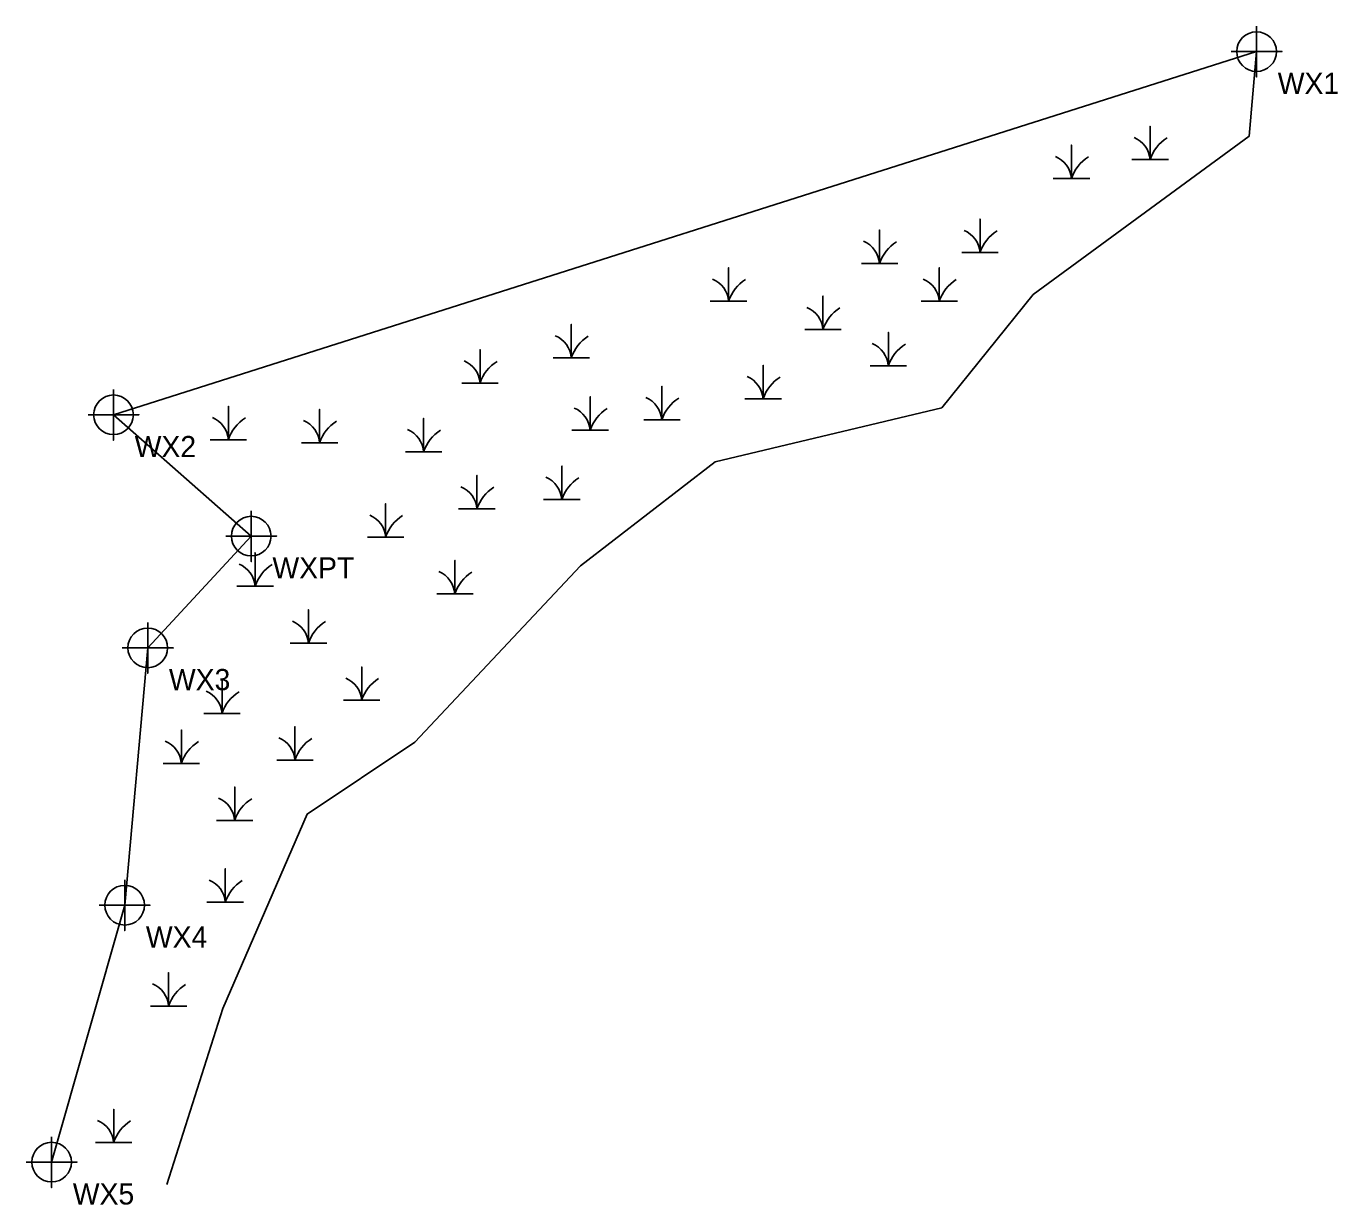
# Model space of a CAD drawing. Extents: x 2171061 to 2188174, y 801741 to 821647.
# Drawn here: x 2178080.8 to 2178235.5, y 808000.7 to 808139.8 of the extents above; entities that cross this region are included whole.
import ezdxf

# ---------------------------------------------------------------- set-up
doc = ezdxf.new("R2010")
doc.units = 0
for name, color, linetype in [('Exist Environmental Wetland Boundary', 7, 'Continuous'), ('Exist Environmental Wetland Boundary Cogo Comment', 7, 'Continuous'), ('Exist Environmental Wetland Boundary Cogo Point CELL', 7, 'Continuous'), ('Exist Hydro Swamp or Marsh', 7, 'Continuous')]:
    doc.layers.add(name, color=color, linetype=linetype)

msp = doc.modelspace()

# ---------------------------------------------------------------- linework, layer by layer
at = {"layer": 'Exist Environmental Wetland Boundary'}
for points in [[(2178225.95, 808136.81), (2178091.09, 808093.95), (2178107.34, 808079.63), (2178095.13, 808066.44), (2178092.41, 808036.07), (2178083.79, 808005.75)], [(2178225.95, 808136.81), (2178225.06, 808126.82), (2178199.61, 808108.15), (2178188.8, 808094.78), (2178162.08, 808088.41), (2178146.17, 808076.11), (2178126.66, 808055.31), (2178113.94, 808046.82), (2178103.97, 808023.9), (2178097.4, 808003.11)]]:
    msp.add_lwpolyline(points, dxfattribs=at)
at = {"layer": 'Exist Environmental Wetland Boundary Cogo Point CELL'}
for points in [[(2178225.95, 808139.81), (2178225.95, 808133.81), (2178225.95, 808136.81), (2178228.95, 808136.81), (2178222.95, 808136.81)], [(2178091.09, 808096.95), (2178091.09, 808090.95), (2178091.09, 808093.95), (2178094.09, 808093.95), (2178088.09, 808093.95)], [(2178107.34, 808082.63), (2178107.34, 808076.63), (2178107.34, 808079.63), (2178110.34, 808079.63), (2178104.34, 808079.63)], [(2178095.13, 808069.44), (2178095.13, 808063.44), (2178095.13, 808066.44), (2178098.13, 808066.44), (2178092.13, 808066.44)], [(2178092.41, 808039.07), (2178092.41, 808033.07), (2178092.41, 808036.07), (2178095.41, 808036.07), (2178089.41, 808036.07)], [(2178083.79, 808008.75), (2178083.79, 808002.75), (2178083.79, 808005.75), (2178086.79, 808005.75), (2178080.79, 808005.75)]]:
    msp.add_lwpolyline(points, dxfattribs=at)
for centre in [(2178225.95, 808136.81), (2178091.09, 808093.95), (2178107.34, 808079.63), (2178095.13, 808066.44), (2178092.41, 808036.07), (2178083.79, 808005.75)]:
    msp.add_circle(centre, 2.34, dxfattribs=at)
at = {"layer": 'Exist Hydro Swamp or Marsh'}
for p, q in [((2178213.38, 808125.85), (2178213.38, 808125.85)), ((2178204.11, 808123.62), (2178204.11, 808123.62)), ((2178193.33, 808114.88), (2178193.33, 808114.88)), ((2178181.47, 808113.59), (2178181.47, 808113.59)), ((2178163.65, 808109.14), (2178163.65, 808109.14)), ((2178188.52, 808109.14), (2178188.52, 808109.14)), ((2178174.79, 808105.79), (2178174.79, 808105.79)), ((2178145.1, 808102.45), (2178145.1, 808102.45)), ((2178182.51, 808101.51), (2178182.51, 808101.51)), ((2178134.34, 808099.48), (2178134.34, 808099.48)), ((2178167.74, 808097.63), (2178167.74, 808097.63)), ((2178147.32, 808093.91), (2178147.32, 808093.91)), ((2178155.79, 808095.15), (2178155.79, 808095.15)), ((2178104.65, 808092.8), (2178104.65, 808092.8)), ((2178115.41, 808092.43), (2178115.41, 808092.43)), ((2178127.68, 808091.36), (2178127.68, 808091.36)), ((2178133.96, 808084.63), (2178133.96, 808084.63)), ((2178143.98, 808085.74), (2178143.98, 808085.74)), ((2178123.2, 808081.29), (2178123.2, 808081.29)), ((2178107.8, 808075.51), (2178107.8, 808075.51)), ((2178131.37, 808074.6), (2178131.37, 808074.6)), ((2178114.09, 808068.78), (2178114.09, 808068.78)), ((2178120.37, 808062.04), (2178120.37, 808062.04)), ((2178103.9, 808060.49), (2178103.9, 808060.49)), ((2178099.1, 808054.6), (2178099.1, 808054.6)), ((2178112.5, 808054.99), (2178112.5, 808054.99)), ((2178105.39, 808047.86), (2178105.39, 808047.86)), ((2178104.27, 808038.21), (2178104.27, 808038.21)), ((2178097.59, 808025.95), (2178097.59, 808025.95)), ((2178091.11, 808009.84), (2178091.11, 808009.84))]:
    msp.add_line(p, q, dxfattribs=at)
for points in [[(2178211.23, 808124.06), (2178213.39, 808124.06), (2178213.39, 808128.01), (2178213.39, 808124.06), (2178215.54, 808124.06)], [(2178201.96, 808121.84), (2178204.11, 808121.84), (2178204.11, 808125.78), (2178204.11, 808121.84), (2178206.26, 808121.84)], [(2178191.18, 808113.1), (2178193.33, 808113.1), (2178193.33, 808117.04), (2178193.33, 808113.1), (2178195.48, 808113.1)], [(2178179.32, 808111.81), (2178181.47, 808111.81), (2178181.47, 808115.76), (2178181.47, 808111.81), (2178183.62, 808111.81)], [(2178161.5, 808107.35), (2178163.65, 808107.35), (2178163.65, 808111.3), (2178163.65, 808107.35), (2178165.81, 808107.35)], [(2178186.37, 808107.35), (2178188.52, 808107.35), (2178188.52, 808111.3), (2178188.52, 808107.35), (2178190.67, 808107.35)], [(2178172.64, 808104.01), (2178174.79, 808104.01), (2178174.79, 808107.96), (2178174.79, 808104.01), (2178176.94, 808104.01)], [(2178142.95, 808100.67), (2178145.1, 808100.67), (2178145.1, 808104.61), (2178145.1, 808100.67), (2178147.25, 808100.67)], [(2178180.36, 808099.73), (2178182.51, 808099.73), (2178182.51, 808103.67), (2178182.51, 808099.73), (2178184.66, 808099.73)], [(2178132.19, 808097.7), (2178134.34, 808097.7), (2178134.34, 808101.64), (2178134.34, 808097.7), (2178136.49, 808097.7)], [(2178165.59, 808095.84), (2178167.74, 808095.84), (2178167.74, 808099.79), (2178167.74, 808095.84), (2178169.89, 808095.84)], [(2178153.64, 808093.36), (2178155.79, 808093.36), (2178155.79, 808097.31), (2178155.79, 808093.36), (2178157.94, 808093.36)], [(2178145.17, 808092.13), (2178147.33, 808092.13), (2178147.33, 808096.07), (2178147.33, 808092.13), (2178149.48, 808092.13)], [(2178102.5, 808091.01), (2178104.65, 808091.01), (2178104.65, 808094.96), (2178104.65, 808091.01), (2178106.8, 808091.01)], [(2178113.26, 808090.64), (2178115.41, 808090.64), (2178115.41, 808094.59), (2178115.41, 808090.64), (2178117.56, 808090.64)], [(2178125.53, 808089.58), (2178127.68, 808089.58), (2178127.68, 808093.52), (2178127.68, 808089.58), (2178129.83, 808089.58)], [(2178141.83, 808083.96), (2178143.99, 808083.96), (2178143.99, 808087.9), (2178143.99, 808083.96), (2178146.14, 808083.96)], [(2178131.81, 808082.84), (2178133.96, 808082.84), (2178133.96, 808086.79), (2178133.96, 808082.84), (2178136.12, 808082.84)], [(2178121.05, 808079.5), (2178123.2, 808079.5), (2178123.2, 808083.45), (2178123.2, 808079.5), (2178125.35, 808079.5)], [(2178105.65, 808073.73), (2178107.8, 808073.73), (2178107.8, 808077.67), (2178107.8, 808073.73), (2178109.95, 808073.73)], [(2178129.22, 808072.82), (2178131.37, 808072.82), (2178131.37, 808076.76), (2178131.37, 808072.82), (2178133.52, 808072.82)], [(2178111.94, 808066.99), (2178114.09, 808066.99), (2178114.09, 808070.94), (2178114.09, 808066.99), (2178116.24, 808066.99)], [(2178118.22, 808060.26), (2178120.37, 808060.26), (2178120.37, 808064.2), (2178120.37, 808060.26), (2178122.52, 808060.26)], [(2178101.75, 808058.71), (2178103.9, 808058.71), (2178103.9, 808062.65), (2178103.9, 808058.71), (2178106.05, 808058.71)], [(2178096.95, 808052.81), (2178099.1, 808052.81), (2178099.1, 808056.76), (2178099.1, 808052.81), (2178101.25, 808052.81)], [(2178110.35, 808053.2), (2178112.5, 808053.2), (2178112.5, 808057.15), (2178112.5, 808053.2), (2178114.65, 808053.2)], [(2178103.24, 808046.08), (2178105.39, 808046.08), (2178105.39, 808050.03), (2178105.39, 808046.08), (2178107.54, 808046.08)], [(2178102.12, 808036.43), (2178104.27, 808036.43), (2178104.27, 808040.37), (2178104.27, 808036.43), (2178106.43, 808036.43)], [(2178095.44, 808024.17), (2178097.59, 808024.17), (2178097.59, 808028.12), (2178097.59, 808024.17), (2178099.75, 808024.17)], [(2178088.96, 808008.06), (2178091.11, 808008.06), (2178091.11, 808012), (2178091.11, 808008.06), (2178093.26, 808008.06)]]:
    msp.add_lwpolyline(points, dxfattribs=at)
for centre, radius, start, end in [((2178210.32, 808123.84), 3.07, 4.1403, 67.535), ((2178217.95, 808122.55), 4.81, 122.1274, 161.6222), ((2178201.04, 808121.61), 3.07, 4.1403, 67.535), ((2178208.67, 808120.32), 4.81, 122.1274, 161.6222), ((2178190.26, 808112.88), 3.07, 4.1403, 67.535), ((2178197.89, 808111.58), 4.81, 122.1274, 161.6222), ((2178178.4, 808111.59), 3.07, 4.1403, 67.535), ((2178186.03, 808110.29), 4.81, 122.1274, 161.6222), ((2178160.59, 808107.13), 3.07, 4.1403, 67.535), ((2178168.22, 808105.84), 4.81, 122.1274, 161.6222), ((2178185.45, 808107.13), 3.07, 4.1403, 67.535), ((2178193.08, 808105.84), 4.81, 122.1274, 161.6222), ((2178171.72, 808103.79), 3.07, 4.1403, 67.535), ((2178179.35, 808102.5), 4.81, 122.1274, 161.6222), ((2178142.03, 808100.45), 3.07, 4.1403, 67.535), ((2178149.66, 808099.15), 4.81, 122.1274, 161.6222), ((2178179.44, 808099.51), 3.07, 4.1403, 67.535), ((2178187.07, 808098.21), 4.81, 122.1274, 161.6222), ((2178131.27, 808097.48), 3.07, 4.1403, 67.535), ((2178138.9, 808096.18), 4.81, 122.1274, 161.6222), ((2178164.67, 808095.62), 3.07, 4.1403, 67.535), ((2178172.3, 808094.33), 4.81, 122.1274, 161.6222), ((2178152.72, 808093.14), 3.07, 4.1403, 67.535), ((2178160.35, 808091.85), 4.81, 122.1274, 161.6222), ((2178144.26, 808091.91), 3.07, 4.1403, 67.535), ((2178151.89, 808090.61), 4.81, 122.1274, 161.6222), ((2178101.58, 808090.79), 3.07, 4.1403, 67.535), ((2178109.21, 808089.5), 4.81, 122.1274, 161.6222), ((2178112.34, 808090.42), 3.07, 4.1403, 67.535), ((2178119.97, 808089.13), 4.81, 122.1274, 161.6222), ((2178124.61, 808089.36), 3.07, 4.1403, 67.535), ((2178132.24, 808088.06), 4.81, 122.1274, 161.6222), ((2178140.92, 808083.74), 3.07, 4.1403, 67.535), ((2178148.55, 808082.44), 4.81, 122.1274, 161.6222), ((2178130.9, 808082.62), 3.07, 4.1403, 67.535), ((2178138.53, 808081.33), 4.81, 122.1274, 161.6222), ((2178120.14, 808079.28), 3.07, 4.1403, 67.535), ((2178127.76, 808077.99), 4.81, 122.1274, 161.6222), ((2178104.73, 808073.5), 3.07, 4.1403, 67.535), ((2178112.36, 808072.21), 4.81, 122.1274, 161.6222), ((2178128.3, 808072.6), 3.07, 4.1403, 67.535), ((2178135.93, 808071.3), 4.81, 122.1274, 161.6222), ((2178111.02, 808066.77), 3.07, 4.1403, 67.535), ((2178118.65, 808065.48), 4.81, 122.1274, 161.6222), ((2178117.31, 808060.04), 3.07, 4.1403, 67.535), ((2178124.93, 808058.74), 4.81, 122.1274, 161.6222), ((2178100.84, 808058.49), 3.07, 4.1403, 67.535), ((2178108.46, 808057.19), 4.81, 122.1274, 161.6222), ((2178096.03, 808052.59), 3.07, 4.1403, 67.535), ((2178103.66, 808051.3), 4.81, 122.1274, 161.6222), ((2178109.43, 808052.98), 3.07, 4.1403, 67.535), ((2178117.06, 808051.69), 4.81, 122.1274, 161.6222), ((2178102.32, 808045.86), 3.07, 4.1403, 67.535), ((2178109.95, 808044.57), 4.81, 122.1274, 161.6222), ((2178101.21, 808036.2), 3.07, 4.1403, 67.535), ((2178108.84, 808034.91), 4.81, 122.1274, 161.6222), ((2178094.53, 808023.95), 3.07, 4.1403, 67.535), ((2178102.16, 808022.66), 4.81, 122.1274, 161.6222), ((2178088.04, 808007.84), 3.07, 4.1403, 67.535), ((2178095.67, 808006.54), 4.81, 122.1274, 161.6222)]:
    msp.add_arc(centre, radius, start, end, dxfattribs=at)

# ---------------------------------------------------------------- texts
at = {"layer": 'Exist Environmental Wetland Boundary Cogo Comment'}
for s, p in [('WX1', (2178228.45, 808131.81)), ('WX2', (2178093.59, 808088.95)), ('WXPT', (2178109.84, 808074.63)), ('WX3', (2178097.63, 808061.45)), ('WX4', (2178094.91, 808031.07)), ('WX5', (2178086.29, 808000.75))]:
    msp.add_text(s, height=2.5, dxfattribs=at).set_placement(p)

doc.saveas('drawing.dxf')
